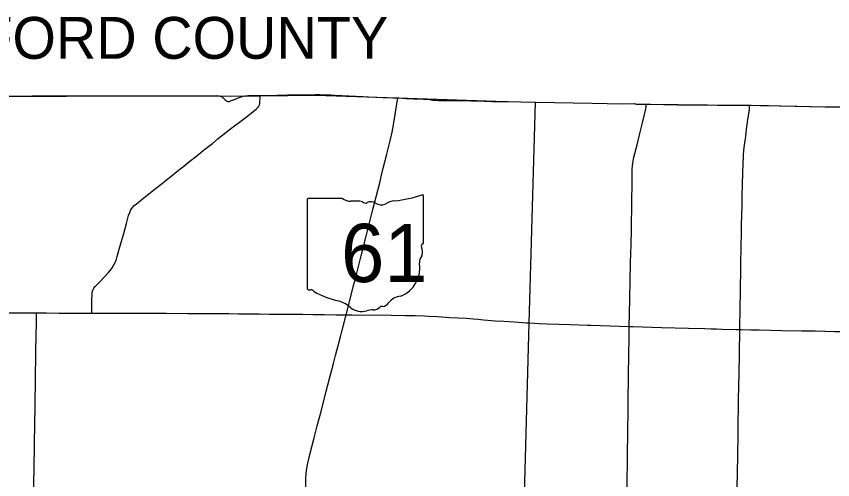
# Model space of a CAD drawing. Extents: x 9078 to 9739, y 4248 to 4966.
# Drawn here: x 9362.4 to 9460, y 4895.4 to 4950.8 of the extents above; entities that cross this region are included whole.
import ezdxf

# ---------------------------------------------------------------- set-up
doc = ezdxf.new("R2010")
doc.units = 0
for name, color, linetype in [('GM_X_Adjacent_County_Text', 7, 'Continuous'), ('GM_X_County', 7, 'Continuous'), ('GM_X_County_Road', 7, 'Continuous'), ('GM_X_State_Route', 7, 'Continuous'), ('GM_X_State_Shield', 7, 'Continuous'), ('GM_X_Township', 7, 'Continuous'), ('GM_X_Township_Road', 7, 'Continuous')]:
    doc.layers.add(name, color=color, linetype=linetype)

msp = doc.modelspace()

# ---------------------------------------------------------------- linework, layer by layer
at = {"layer": 'GM_X_County'}
msp.add_lwpolyline([(9358.306, 4941.216), (9378.385, 4941.303), (9386.499, 4941.289), (9389.718, 4941.236), (9391.544, 4941.287), (9398.123, 4941.39), (9407.956, 4941.035), (9420.93, 4940.605), (9424.443, 4940.552), (9431.223, 4940.396), (9434.793, 4940.327), (9436.237, 4940.39), (9436.384, 4940.34), (9436.523, 4940.304), (9436.662, 4940.286), (9437.032, 4940.276), (9437.668, 4940.28), (9439.771, 4940.262), (9441.454, 4940.236), (9442.833, 4940.213), (9443.946, 4940.204), (9446.203, 4940.177), (9450.031, 4940.191), (9460.879, 4939.952)], dxfattribs=at)
at = {"layer": 'GM_X_County_Road'}
for points in [[(9358.303, 4941.208), (9358.786, 4941.205), (9359.614, 4941.218), (9361.249, 4941.254), (9364.287, 4941.28), (9366.75, 4941.288), (9368.145, 4941.292), (9369.623, 4941.295), (9371.265, 4941.294), (9372.086, 4941.291), (9373.317, 4941.303), (9374.22, 4941.301), (9375.697, 4941.287), (9377.011, 4941.294), (9378.161, 4941.291), (9378.361, 4941.292)], [(9378.361, 4941.292), (9378.981, 4941.296), (9380.212, 4941.301), (9380.869, 4941.307), (9382.018, 4941.305), (9383.086, 4941.304), (9384.4, 4941.307), (9385.713, 4941.31), (9386.286, 4941.314)], [(9435.667, 4913.71), (9435.689, 4915.18), (9435.726, 4917.066), (9435.812, 4921.332), (9435.868, 4923.546), (9435.915, 4925.268), (9435.977, 4928.713), (9436.007, 4930.763), (9436.025, 4932.486), (9436.049, 4932.975), (9436.109, 4933.462), (9436.202, 4933.943), (9436.589, 4935.453), (9436.92, 4936.806), (9437.228, 4938.082), (9437.641, 4939.754), (9437.688, 4940.007), (9437.697, 4940.104), (9437.692, 4940.174), (9437.683, 4940.284)], [(9436.256, 4940.393), (9436.403, 4940.344), (9436.542, 4940.308), (9436.68, 4940.289), (9437.051, 4940.279), (9437.683, 4940.284)], [(9448.873, 4913.349), (9448.877, 4913.657), (9448.913, 4915.791), (9448.947, 4918.006), (9448.995, 4920.713), (9449.051, 4923.667), (9449.069, 4924.569), (9449.09, 4925.879), (9449.116, 4927.109), (9449.146, 4928.09), (9449.156, 4928.746), (9449.161, 4929.32), (9449.192, 4930.715), (9449.233, 4932.027), (9449.268, 4933.176), (9449.321, 4934.158), (9449.372, 4934.813), (9449.444, 4935.384), (9449.525, 4935.95), (9449.597, 4936.434), (9449.687, 4937.248), (9449.856, 4938.466), (9450.018, 4939.603), (9450.041, 4939.927), (9450.031, 4939.988), (9450.012, 4940.038), (9449.975, 4940.108), (9449.932, 4940.168)], [(9358.164, 4915.331), (9358.836, 4915.332), (9361.379, 4915.328), (9362.443, 4915.341), (9364.575, 4915.337), (9364.794, 4915.334)], [(9364.415, 4888.64), (9364.423, 4889.76), (9364.435, 4891.154), (9364.45, 4892.794), (9364.475, 4895.089), (9364.501, 4896.728), (9364.582, 4902.221), (9364.605, 4903.943), (9364.624, 4905.009), (9364.648, 4906.648), (9364.66, 4907.468), (9364.678, 4908.533), (9364.69, 4909.352), (9364.717, 4910.991), (9364.734, 4912.385), (9364.769, 4914.27), (9364.791, 4915.091), (9364.792, 4915.174), (9364.794, 4915.334)], [(9364.794, 4915.334), (9365.967, 4915.33), (9367.443, 4915.322), (9369.493, 4915.32), (9371.214, 4915.313), (9371.385, 4915.313)], [(9371.385, 4915.313), (9371.952, 4915.313), (9374.822, 4915.317), (9376.872, 4915.316), (9378.512, 4915.307), (9380.316, 4915.3), (9382.858, 4915.283), (9385.974, 4915.253), (9387.777, 4915.247), (9388.925, 4915.238), (9389.581, 4915.233), (9391.465, 4915.219), (9392.613, 4915.205), (9394.991, 4915.181), (9396.631, 4915.168), (9397.86, 4915.15), (9399.172, 4915.132), (9400.566, 4915.125), (9401.546, 4915.122), (9401.76, 4915.122), (9401.814, 4915.122)], [(9435.305, 4888.55), (9435.314, 4889.065), (9435.361, 4892.264), (9435.411, 4894.889), (9435.424, 4896.121), (9435.438, 4896.693), (9435.461, 4897.67), (9435.464, 4898.482), (9435.468, 4898.959), (9435.485, 4900.498), (9435.53, 4904.353), (9435.585, 4908.208), (9435.604, 4910.013), (9435.657, 4912.719), (9435.665, 4913.622), (9435.667, 4913.71)], [(9448.526, 4891.131), (9448.533, 4891.673), (9448.551, 4893.232), (9448.572, 4894.709), (9448.595, 4896.103), (9448.679, 4900.698), (9448.699, 4902.42), (9448.716, 4903.815), (9448.724, 4904.964), (9448.768, 4906.602), (9448.8, 4907.996), (9448.828, 4910.458), (9448.873, 4913.349)], [(9448.873, 4913.349), (9449.05, 4913.345), (9450.197, 4913.319), (9451.18, 4913.3), (9453.886, 4913.251), (9456.264, 4913.204), (9457.904, 4913.175), (9460.2, 4913.132), (9460.935, 4913.115), (9462.985, 4913.085), (9465.033, 4913.051), (9466.919, 4913.019), (9468.066, 4913.001), (9468.72, 4912.983), (9470.103, 4912.943), (9470.436, 4912.936), (9471.338, 4912.913), (9472.65, 4912.911), (9473.963, 4912.888), (9474.455, 4912.873), (9474.537, 4912.869), (9474.658, 4912.863)]]:
    msp.add_lwpolyline(points, dxfattribs=at)
at = {"layer": 'GM_X_State_Route'}
for points in [[(9406.201, 4932.47), (9406.205, 4932.487), (9406.669, 4934.315), (9407.109, 4936.066), (9407.304, 4936.947), (9407.463, 4937.836), (9407.653, 4939.052), (9407.994, 4941.04)], [(9402.702, 4918.599), (9402.875, 4919.284), (9403.607, 4922.146), (9404.245, 4924.692), (9405.015, 4927.712), (9405.822, 4930.893), (9406.132, 4932.168), (9406.201, 4932.47)], [(9401.332, 4913.265), (9401.411, 4913.563), (9401.814, 4915.122), (9402.171, 4916.501), (9402.702, 4918.599)], [(9399.437, 4905.985), (9399.942, 4907.928), (9400.288, 4909.28), (9400.535, 4910.231), (9400.971, 4911.898), (9401.171, 4912.655), (9401.332, 4913.265)], [(9396.922, 4887.013), (9396.96, 4887.793), (9397.011, 4889.434), (9397.014, 4890.419), (9396.984, 4892.715), (9396.975, 4894.273), (9396.987, 4895.503), (9397.025, 4896.157), (9397.094, 4896.725), (9397.214, 4897.368), (9397.459, 4898.405), (9397.976, 4900.389), (9398.349, 4901.817), (9398.808, 4903.562), (9399.437, 4905.985)]]:
    msp.add_lwpolyline(points, dxfattribs=at)
at = {"layer": 'GM_X_State_Shield'}
for p, q in [((9397.145, 4928.845), (9397.145, 4918.279)), ((9401.359, 4929.027), (9397.282, 4929.027)), ((9411.067, 4923.762), (9411.067, 4929.289)), ((9411.065, 4923.763), (9411.067, 4923.762))]:
    msp.add_line(p, q, dxfattribs=at)
for centre, radius, start, end in [((9397.305, 4928.868), 0.161, 98.1301, 188.1301), ((9402.33, 4930.254), 1.564, 231.61951, 271.11188), ((9402.849, 4923.095), 5.616, 80.48669, 94.98827), ((9404.124, 4928.923), 0.451, 219.79206, 297.10237), ((9404.786, 4927.701), 0.938, 54.46668, 119.14113), ((9407.991, 4925.8), 2.97, 97.34618, 120.76885), ((9406.108, 4943.433), 14.764, 275.84447, 288.90645), ((9410.912, 4929.312), 0.155, 351.86209, 97.738), ((9405.997, 4929.376), 1.129, 233.85621, 294.82819), ((9410.901, 4923.74), 0.166, 289.60381, 7.73413), ((9411.031, 4923.356), 0.24, 107.94398, 210.33697), ((9409.505, 4922.657), 1.44, 340.03296, 23.64957), ((9411.622, 4921.448), 1.048, 136.8065, 186.92959), ((9406.935, 4920.745), 3.693, 292.30889, 8.98584), ((9397.306, 4918.256), 0.163, 171.95839, 258.30661), ((9397.331, 4919.337), 1.242, 267.33899, 280.60386), ((9397.585, 4917.669), 0.448, 29.74838, 93.27175), ((9403.238, 4927.163), 10.661, 240.41292, 257.1985), ((9408.492, 4915.312), 2.022, 94.40312, 142.57675), ((9400.059, 4913.532), 3.336, 47.18416, 75.83597), ((9403.667, 4917.617), 2.117, 230.70037, 286.29184), ((9405.045, 4916.826), 1.128, 268.77702, 315.54927), ((9406.065, 4915.802), 0.318, 65.75173, 132.64842), ((9405.929, 4917.255), 1.193, 282.87319, 323.27711), ((9404.89, 4913.964), 1.739, 85.69512, 111.20995)]:
    msp.add_arc(centre, radius, start, end, dxfattribs=at)
at = {"layer": 'GM_X_Township'}
msp.add_lwpolyline([(9421.269, 4808.362), (9421.979, 4834.777), (9422.27, 4847.941), (9422.446, 4861.285), (9422.928, 4886.346), (9423.704, 4914.119), (9424.443, 4940.552)], dxfattribs=at)
at = {"layer": 'GM_X_Township_Road'}
for points in [[(9382.094, 4932.647), (9382.413, 4932.899), (9382.925, 4933.308), (9384.134, 4934.29), (9384.71, 4934.749), (9385.552, 4935.402), (9385.809, 4935.605), (9386.51, 4936.171), (9387.994, 4937.334), (9389.682, 4938.633), (9390.849, 4939.537), (9391.102, 4939.745), (9391.269, 4939.925), (9391.36, 4940.061), (9391.429, 4940.209), (9391.478, 4940.365), (9391.504, 4940.526), (9391.528, 4941.098), (9391.525, 4941.189), (9391.52, 4941.267), (9391.507, 4941.333)], [(9386.286, 4941.314), (9386.517, 4941.304), (9386.627, 4941.291), (9386.751, 4941.265), (9386.884, 4941.214), (9386.949, 4941.18), (9387.065, 4941.089), (9387.339, 4940.82), (9387.463, 4940.716), (9387.528, 4940.668), (9387.601, 4940.634), (9387.68, 4940.616), (9387.759, 4940.617), (9387.839, 4940.631), (9387.917, 4940.651), (9387.994, 4940.676), (9388.454, 4940.855), (9388.615, 4940.918), (9389.143, 4941.126), (9389.26, 4941.168), (9389.506, 4941.241), (9389.728, 4941.286)], [(9389.728, 4941.286), (9389.826, 4941.298), (9389.866, 4941.302), (9389.98, 4941.311), (9390.145, 4941.32)], [(9390.145, 4941.32), (9390.224, 4941.324), (9390.633, 4941.327), (9391.507, 4941.333)], [(9391.507, 4941.333), (9392.285, 4941.339), (9394.78, 4941.393), (9395.799, 4941.414), (9398.098, 4941.446)], [(9398.098, 4941.446), (9398.662, 4941.44), (9399.399, 4941.422), (9399.973, 4941.396), (9400.463, 4941.368), (9403.824, 4941.221), (9404.479, 4941.184), (9405.367, 4941.137), (9406.185, 4941.1), (9407.406, 4941.053), (9407.794, 4941.045), (9407.994, 4941.04)], [(9407.994, 4941.04), (9408.121, 4941.036), (9408.938, 4940.989), (9409.049, 4940.984)], [(9409.049, 4940.984), (9409.43, 4940.968), (9409.893, 4940.949)], [(9409.893, 4940.949), (9410.41, 4940.928), (9410.725, 4940.917), (9411.047, 4940.903), (9411.453, 4940.874), (9411.779, 4940.838), (9412.185, 4940.786), (9412.513, 4940.755), (9412.859, 4940.731), (9413.211, 4940.725)], [(9413.211, 4940.725), (9413.649, 4940.717), (9414.64, 4940.727), (9415.253, 4940.717), (9416.041, 4940.719), (9416.697, 4940.712), (9417.106, 4940.703), (9417.842, 4940.679), (9418.333, 4940.661), (9419.235, 4940.626), (9419.282, 4940.624)], [(9419.282, 4940.624), (9419.891, 4940.606), (9420.466, 4940.601), (9420.795, 4940.611), (9421.041, 4940.629), (9421.181, 4940.643)], [(9437.683, 4940.284), (9438.201, 4940.289), (9439.79, 4940.266)], [(9439.79, 4940.266), (9441.473, 4940.239)], [(9441.473, 4940.239), (9442.306, 4940.227), (9442.852, 4940.217)], [(9442.852, 4940.217), (9442.962, 4940.215), (9443.863, 4940.209), (9443.965, 4940.208)], [(9443.965, 4940.208), (9445.011, 4940.201), (9446.193, 4940.186)], [(9446.193, 4940.186), (9447.869, 4940.171), (9448.92, 4940.171), (9449.164, 4940.172), (9449.653, 4940.169), (9449.932, 4940.168)], [(9449.932, 4940.168), (9450.144, 4940.167), (9450.222, 4940.166)], [(9450.222, 4940.166), (9451.301, 4940.156), (9452.304, 4940.138), (9453.773, 4940.106), (9455.69, 4940.07), (9457.422, 4940.034), (9459.585, 4939.989), (9460.832, 4939.959)], [(9371.385, 4915.313), (9371.386, 4915.471), (9371.398, 4916.865), (9371.417, 4917.603), (9371.451, 4917.846), (9371.497, 4918.002), (9371.564, 4918.15), (9371.652, 4918.288), (9371.807, 4918.479), (9372.427, 4919.135), (9373.383, 4920.15), (9373.643, 4920.466), (9373.826, 4920.738), (9374.032, 4921.092), (9374.216, 4921.458), (9374.339, 4921.761), (9374.434, 4922.075), (9374.672, 4922.945), (9374.991, 4924.047), (9375.213, 4924.836), (9375.539, 4926.021), (9375.8, 4926.97), (9375.929, 4927.359), (9376.03, 4927.583), (9376.153, 4927.796), (9376.3, 4927.992), (9376.469, 4928.17), (9376.72, 4928.382), (9377.431, 4928.937), (9378.188, 4929.526), (9378.826, 4930.037), (9380.042, 4931.009), (9381.066, 4931.828), (9381.577, 4932.238), (9382.094, 4932.647)], [(9401.814, 4915.122), (9402.502, 4915.111), (9407.178, 4915.057), (9408.818, 4915.036), (9409.143, 4915.043), (9409.716, 4915.035), (9410.044, 4915.022), (9411.191, 4914.984), (9411.682, 4914.957), (9412.746, 4914.893), (9414.219, 4914.794), (9416.186, 4914.699), (9417.004, 4914.64), (9417.574, 4914.584), (9418.223, 4914.506), (9419.615, 4914.409), (9420.665, 4914.346), (9421.881, 4914.277), (9423.353, 4914.164), (9423.68, 4914.153)], [(9423.68, 4914.153), (9424.312, 4914.11), (9424.337, 4914.108)], [(9424.337, 4914.108), (9424.888, 4914.074)], [(9424.888, 4914.074), (9425.827, 4914.033), (9427.222, 4913.982), (9428.617, 4913.941), (9430.668, 4913.88), (9431.078, 4913.866), (9432.226, 4913.829), (9435.667, 4913.71)], [(9435.667, 4913.71), (9436.083, 4913.696), (9439.53, 4913.599), (9442.729, 4913.501), (9444.699, 4913.455), (9445.438, 4913.432), (9446.094, 4913.414), (9446.751, 4913.408), (9448.392, 4913.362), (9448.873, 4913.349)]]:
    msp.add_lwpolyline(points, dxfattribs=at)

# ---------------------------------------------------------------- texts
at = {"layer": 'GM_X_Adjacent_County_Text'}
msp.add_text('CRAWFORD COUNTY', height=5, dxfattribs=at).set_placement((9337.39, 4945.724))
at = {"layer": 'GM_X_State_Shield'}
msp.add_text('61', height=6.961, dxfattribs=at).set_placement((9401.196, 4919.024))

doc.saveas('drawing.dxf')
